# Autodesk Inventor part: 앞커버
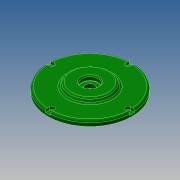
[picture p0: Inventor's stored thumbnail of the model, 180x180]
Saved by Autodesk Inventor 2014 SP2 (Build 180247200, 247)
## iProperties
Created: 2016-11
Part Number: 앞커버
Material: 알루미늄 6061
Document SubType Name: Modeling
Designer: mduedu
Density: 2.71 g/cm^3
Mass: 394.831 g
Surface Area: 366.671 cm^2
Volume: 145.694 cm^3
Appearance: 진녹색
Author: mduedu
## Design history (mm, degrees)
sketch "스케치1"
  geometry: L1 (22, -12.5)-(22, -30); L2 (22, -30)-(16, -33.464); L3 (16, -33.464)-(16, -65); L4 (16, -65)-(8, -65); L5 (8, -65)-(8, -53); L6 (8, -53)-(0, -53); L7 (0, -53)-(0, -14); L8 (0, 0)-(22, 0); L9 (8, -14)-(8, -7); L10 (8, -7)-(14.5, -7); L11 (14.5, -7)-(14.5, -12.5); L12 (0, -14)-(8, -14); L13 (14.5, -12.5)-(22, -12.5)
  constraints: 26 end point, 8 parallel, 3 perpendicular, 2 horizontal, 2 vertical alignment, 1 collinear
  dimensions: "d0" = 8 distance of L5.end L6.end; "d2" = 8 distance of L3.end L4.end; "d3" = 6 distance between parallel lines of L1 L3; "d4" = 120 deg angle of L3 L2; "d5" = 7.5 distance of L11.end L1.start; "d6" = 60 diameter of L1.end L8; "d7" = 14 diameter of L10 L8; "d8" = 28 diameter of L12 L8; "d9" = 25 diameter of L13 L8; "d10" = 106 diameter of L6 L8; "d11" = 130 diameter of L4 L8
revolve "회전1" sketch "스케치1" stored, may be unused: angle "d12" = 90 deg
fillet "모깎기1" dims "d13" = 0.3
fillet "모깎기2" dims "d14" = 3
chamfer "모따기1" distance "d15" = 1; stored, may be unused: second distance "d16" = 2, angle "d17" = 45 deg
fillet "모깎기3" dims "d18" = 0.3
chamfer "모따기2" distance "d36" = 2; stored, may be unused: second distance "d37" = 2, angle "d38" = 30 deg
sketch "스케치3"
  geometry: C1 r 65 at (0, 0) reference; A1 r 59 centre (0, 0) between (0, 59) and (59, 0); 2 further points
  constraints: 4 point on circle, 2 horizontal alignment, 2 vertical alignment, 1 centre point, 1 coincident
  dimensions: "d33" = 118 diameter of A1
sketch "스케치4"
  geometry: 4 further points
  constraints: 4 other
hole "구멍2" sketch "스케치4" at (0, 59), (-59, 0), (59, 0), (0, -59) diameter "d39" = 4.5; stored, may be unused: countersink angle "d43" = 90 deg, drill point angle "d45" = 0 deg; dims "d40" = 6, "d41" = 8, "d42" = 4.6, "d44" = 8
sketch "스케치6"
  geometry: L1 (-4, 5.877)-(-4, 0); L2 (4, 5.877)-(4, 0); A1 r 4 centre (0, 0) between (-2.712, 2.941) and (2.712, 2.941) reference; A2 r 65 centre (0, -59) between (-4, 5.877) and (4, 5.877) reference; 1 further point
  constraints: 4 end point, 4 point on circle, 2 tangent, 2 vertical
extrude "돌출2" cut sketch "스케치6" stored distance "d51" = 10; taper "d52" = 0 deg
sketch "스케치5"
  geometry: C1 r 22 at (0, 0); C2 r 45 at (0, 0); 1 further point
  constraints: 2 centre point, 2 coincident
  dimensions: "d46" = 44 diameter of C1; "d47" = 90 diameter of C2
extrude "돌출1" cut sketch "스케치5" distance "d48" = 8; taper "d49" = 0 deg
fillet "모깎기4" dims "d50" = 3
node "솔리드1"
pattern_circular "원형 패턴1" dims angle "d54" = 360 deg
